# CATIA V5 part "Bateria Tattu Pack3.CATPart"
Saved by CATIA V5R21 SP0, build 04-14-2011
Part number: Bateria Tattu Pack3
Material "DS Red": density 7860 kg/m3, Young's modulus 2e+11 Pa, Poisson ratio 0.266
Bounding box of the stored display mesh (mm): x 173.5 to 386.5, y 42.5 to 111.5, z -48 to 48
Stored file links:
  C:\Users\rodri\OneDrive\Área de Trabalho\FACULDADE\3°semestre\Sistemas Aeroespaciais\Projeto de avião 2019-02\CAD\Bateria Tattu Pack3.CATPart
  C:\Program Files (x86)\Dassault Systemes\B21\intel_a\startup\materials\red_env_512x512.jpg
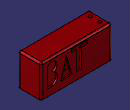
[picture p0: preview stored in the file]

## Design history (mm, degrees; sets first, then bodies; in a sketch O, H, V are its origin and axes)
Body1 (main body), material "DS Red"
  Sketch1 on yz-plane, origin (0, 0, 0), H (0, 1, 0), V (0, 0, 1)
    line L1 (-106.5, 48) -> (106.5, 48)
    line L2 (106.5, 48) -> (106.5, -48)
    line L3 (106.5, -48) -> (-106.5, -48)
    line L4 (-106.5, -48) -> (-106.5, 48)
    distance L4 L2 = 213
    distance L3 L1 = 96
    horizontal: L1 H, L3 H
    vertical: L2 V, L4 V
    symmetry: L4 L2 V, L3 L1 H
  Pad1: profile Sketch1, direction (1, 0, 0), length 34.5, mirrored extent
  Fillet1: radius 5, on edge [face of Pad1 from Sketch1.L1 | face of Pad1 from Sketch1.L2]
  Fillet2: radius 5, on edge [face of Pad1 from Sketch1.L2 | end face of Pad1]; edge [face of Pad1 from Sketch1.L1 | end face of Pad1]; edge [start face of Pad1 | face of Pad1 from Sketch1.L1]; edge [face of Pad1 from Sketch1.L4 | face of Pad1 from Sketch1.L1]; edge [face of Pad1 from Sketch1.L4 | end face of Pad1]; edge [start face of Pad1 | face of Pad1 from Sketch1.L2]
  Fillet3: radius 5, on edge [start face of Pad1 | face of Pad1 from Sketch1.L4]
  Sketch2 on face of Pad1 from Sketch1.L1, origin (0, 0, 48), H (1, 0, 0), V (0, 1, 0)
    circle A1 centre (-14.5, -90) radius 5
    point P1 (-14.5, -90)
    circle A2 centre (14.5, -90) radius 5
    point P2 (14.5, -90)
    reference projected line E1 (-34.5, 101.5) -> (-34.5, -106.5) from edge [start face of Pad1 | face of Fillet2]
    distance P1 E1 = 20
    radius A1 = 5
    radius A2 = 5
    distance A2 H = 85
    symmetry: P1 P2 V
  Pocket1: profile Sketch2, direction (0, 0, -1), length 10
  Sketch3 on start face of Pad1, origin (-34.5, 0, 0), H (0, -1, 0), V (0, 0, 1)
    line L1 (-86.2435, -27.0111) -> (-86.2435, 30.4896)
    arc A1 centre (-73.5977, 21.6671) radius 15.4193 from (-86.2435, 30.4896) to (-68.3938, 7.1525) cw
    arc A2 centre (-74.0974, -9.6616) radius 17.7552 from (-68.3938, 7.1525) to (-70.3235, -27.0111) cw
    line L2 (-70.3235, -27.0111) -> (-86.2435, -27.0111)
    point P7 (-46.9259, -27.0111)
    line L3 (-46.9259, -27.0111) -> (-30.0411, 30.4896)
    line L4 (-30.0411, 30.4896) -> (-13.3975, -27.0111)
    point P9 (-13.3975, -27.0111)
    line L5 (-13.3975, -27.0111) -> (-46.9259, -27.0111)
    point P10 (-37.5187, 0)
    line L6 (-37.5187, 0) -> (-23.046, 0)
    line L7 (-23.046, 0) -> (-23.046, -5.3581)
    line L8 (-23.046, -5.3581) -> (-37.5187, -5.3581)
    line L9 (-37.5187, -5.3581) -> (-37.5187, 0)
    point P14 (0, 30.4896)
    line L10 (0, 30.4896) -> (0, -27.0111)
    point P15 (0, -27.0111)
    line L11 (0, -27.0111) -> (14.58, -26.9312)
    line L12 (14.58, -26.9312) -> (14.2654, 30.4896)
    line L13 (14.2654, 30.4896) -> (32.674, 30.4896)
    line L14 (32.674, 30.4896) -> (32.674, 40.1131)
    line L15 (32.674, 40.1131) -> (-15.086, 40.1131)
    line L16 (-15.086, 40.1131) -> (-15.086, 30.4896)
    point P21 (-15.086, 30.4896)
    line L17 (-15.086, 30.4896) -> (0, 30.4896)
    vertical: L1 V, L7 V, L9 V, L10 V, L14 V, L16 V
    horizontal: L2 H, L5 H, L6 H, L8 H, L13 H, L15 H, L17 H
    coincidence: P7 L2, P9 L2, P10 H, P14 V, P15 L2, P21 L13
    tangency: L11 A2
  Pocket2: profile Sketch3, direction (1, 0, 0), length 5
  Sketch4 on end face of Pad1, origin (34.5, 0, 0), H (0, 1, 0), V (0, 0, 1)
    axis line L1 (-201.212, 0) -> (227.9274, 0)
    point P1 (-201.212, 0)
    coincidence: P1 H
    horizontal: L1 H
  Rotate1: Axis edge [start face of Pad1 | face of Fillet2], Angle 90, ToTransfor Pocket2
  Rotate2: Axis edge [face of Pad1 from Sketch1.L4 | face of Fillet3], Angle 90, ToTransfor Rotate1
  Rotate3: Axis edge [face of Pad1 from Sketch1.L4 | face of Fillet3], Angle 90, ToTransfor Rotate2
